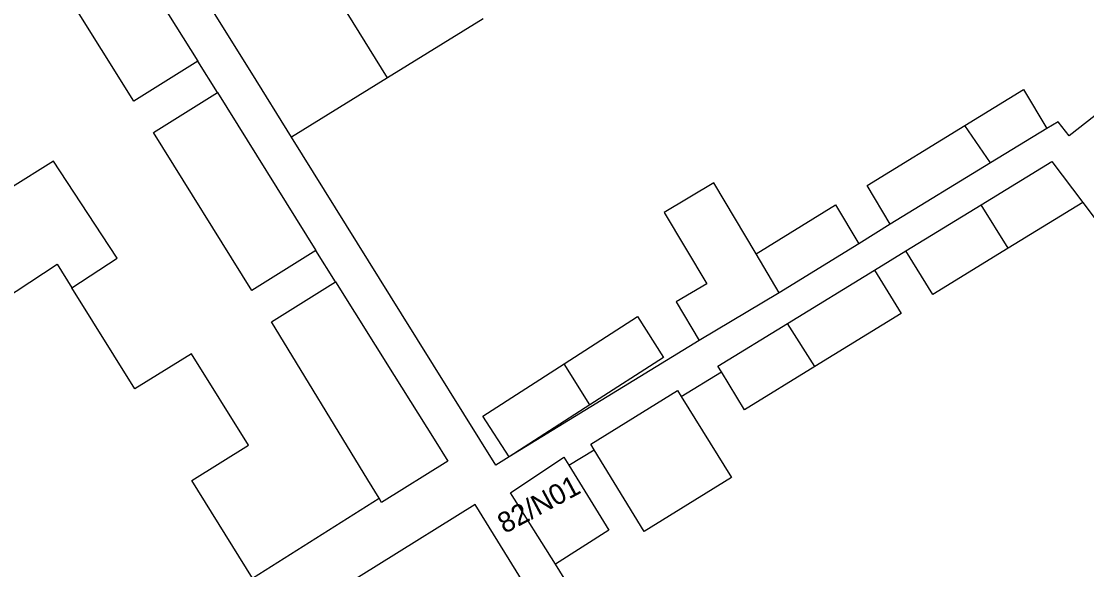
# Model space of a CAD drawing. Extents: x 160379 to 161131, y 383940 to 384849.
# Drawn here: x 160667.2 to 160719.3, y 384308.5 to 384335.4 of the extents above; entities that cross this region are included whole.
import ezdxf

# ---------------------------------------------------------------- set-up
doc = ezdxf.new("R2010")
doc.units = 0
for name, color, linetype in [('IMGEO_Pand', 7, 'Continuous'), ('IMGEO_Pand_nummerreeks', 7, 'Continuous'), ('IMGEO_Voetpad_open', 7, 'Continuous')]:
    doc.layers.add(name, color=color, linetype=linetype)

msp = doc.modelspace()

# ---------------------------------------------------------------- linework, layer by layer
at = {"layer": 'IMGEO_Pand'}
for points in [[(160685.128, 384332.617), (160679.505, 384341.713)], [(160675.859, 384333.436), (160672.731, 384331.481), (160667.904, 384339.208)], [(160672.911, 384338.155), (160675.859, 384333.436)], [(160680.44, 384329.719), (160678.491, 384332.853), (160675.851, 384337.098)], [(160689.816, 384335.515), (160685.128, 384332.617)], [(160685.128, 384332.617), (160680.44, 384329.719)], [(160681.625, 384324.161), (160678.497, 384322.206), (160673.683, 384329.943), (160676.811, 384331.898)], [(160676.811, 384331.898), (160681.625, 384324.161)], [(160713.375, 384330.286), (160716.245, 384332.044), (160717.382, 384330.138)], [(160669.69, 384322.34), (160671.914, 384323.799), (160671.166, 384324.939), (160668.802, 384328.539), (160666.661, 384327.206), (160665.387, 384326.413), (160662.76, 384330.631)], [(160709.726, 384325.448), (160708.589, 384327.354), (160713.375, 384330.286)], [(160714.627, 384328.45), (160713.375, 384330.286)], [(160717.382, 384330.138), (160714.627, 384328.45)], [(160714.627, 384328.45), (160709.726, 384325.448)], [(160714.166, 384326.409), (160717.624, 384328.531), (160719.144, 384326.516)], [(160703.16, 384324.007), (160701.092, 384327.474), (160698.671, 384326.03), (160700.754, 384322.537), (160699.259, 384321.646), (160700.381, 384319.765)], [(160719.144, 384326.516), (160715.5, 384324.283)], [(160703.16, 384324.007), (160707.044, 384326.398), (160708.181, 384324.492)], [(160710.484, 384324.15), (160714.166, 384326.409)], [(160715.5, 384324.283), (160714.166, 384326.409)], [(160708.181, 384324.492), (160704.297, 384322.101)], [(160704.297, 384322.101), (160703.16, 384324.007)], [(160715.5, 384324.283), (160711.806, 384322.02), (160710.484, 384324.15)], [(160660.93, 384318.218), (160668.97, 384323.497), (160669.69, 384322.34)], [(160704.692, 384320.591), (160708.958, 384323.206)], [(160708.958, 384323.206), (160710.266, 384321.076), (160706.034, 384318.483)], [(160678.534, 384308.131), (160675.562, 384312.906), (160678.335, 384314.633), (160675.545, 384319.115), (160672.772, 384317.389), (160669.69, 384322.34)], [(160684.723, 384312.04), (160684.177, 384312.936), (160679.461, 384320.681), (160682.589, 384322.636)], [(160682.589, 384322.636), (160685.463, 384318.044), (160687.41, 384314.923), (160688.08, 384313.85), (160684.848, 384311.834), (160684.723, 384312.04)], [(160704.297, 384322.101), (160700.381, 384319.765)], [(160693.778, 384318.624), (160697.357, 384320.929), (160698.641, 384318.936), (160695.025, 384316.607)], [(160701.468, 384318.233), (160701.299, 384318.512), (160704.692, 384320.591)], [(160706.034, 384318.483), (160704.692, 384320.591)], [(160691.087, 384314.071), (160689.803, 384316.064), (160693.778, 384318.624)], [(160695.025, 384316.607), (160693.778, 384318.624)], [(160706.034, 384318.483), (160702.592, 384316.373), (160701.468, 384318.233)], [(160695.244, 384314.41), (160695.072, 384314.691), (160699.324, 384317.309), (160699.506, 384317.015)], [(160695.025, 384316.607), (160691.087, 384314.071)], [(160699.506, 384317.015), (160701.966, 384313.052), (160697.685, 384310.417), (160695.244, 384314.41)], [(160693.345, 384308.805), (160691.146, 384312.301), (160693.767, 384314.049), (160694.01, 384313.653)], [(160694.01, 384313.653), (160695.954, 384310.482), (160693.345, 384308.805)], [(160693.226, 384305.58), (160689.416, 384311.726), (160679.992, 384305.865), (160676.071, 384303.426), (160671.781, 384300.758)]]:
    msp.add_lwpolyline(points, dxfattribs=at)
at = {"layer": 'IMGEO_Voetpad_open'}
for points in [[(160676.811, 384331.898), (160675.859, 384333.436)], [(160721.914, 384332.466), (160718.478, 384329.78), (160717.944, 384330.463), (160717.382, 384330.138)], [(160691.087, 384314.071), (160690.433, 384313.65), (160685.818, 384321.071), (160680.44, 384329.719)], [(160719.144, 384326.516), (160728.494, 384314.118)], [(160709.726, 384325.448), (160708.181, 384324.492)], [(160682.589, 384322.636), (160681.625, 384324.161)], [(160708.958, 384323.206), (160710.484, 384324.15)], [(160700.381, 384319.765), (160691.087, 384314.071)], [(160699.506, 384317.015), (160701.468, 384318.233)], [(160694.01, 384313.653), (160695.244, 384314.41)], [(160678.534, 384308.131), (160684.723, 384312.04)], [(160700.713, 384296.924), (160693.345, 384308.805)]]:
    msp.add_lwpolyline(points, dxfattribs=at)

# ---------------------------------------------------------------- texts
at = {"layer": 'IMGEO_Pand_nummerreeks'}
msp.add_text('82/N01', height=1, rotation=28.2984, dxfattribs=at).set_placement((160690.864, 384310.284))

doc.saveas('drawing.dxf')
